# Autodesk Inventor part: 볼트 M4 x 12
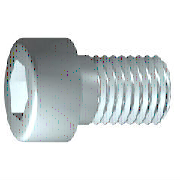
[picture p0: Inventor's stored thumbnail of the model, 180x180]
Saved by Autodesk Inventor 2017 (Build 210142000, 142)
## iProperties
IsCustomPart: 0
Created: 2012-02
Part Number: 볼트 M4 x 12
Material: 스테인리스강
Description: 6각 소켓 머리 캡 나사
Document SubType Name: Modeling
Standard: ISO 4762
Designer: mduedu
Standard Revision: Fourth edition 2004-03-01
Standards Organization: ISO
Language: ko-KR
Size Designation: M4 x 8
Categories: <MemberInstance><Categories><Category DisplayName="조임쇠" InternalName="e4da775c-781d-43d5-af7c-5136215cf5a6" Mnemonic="FSTN"><Category DisplayName="볼트" InternalN
Density: 8.08 g/cm^3
Mass: 2.2972 g
Surface Area: 3.30853 cm^2
Volume: 0.284306 cm^3
Appearance: 반광택
Author: mduedu
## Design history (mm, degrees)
sketch "스케치1"
  geometry: L1 (-1, 0)-(12, 0); L2 (12, 0)-(12, 2); L3 (12, 2)-(1.75, 2); L4 (1.75, 2)-(1.32, 2); L5 (1.32, 2)-(0, 2); L6 (0, 2)-(0, 3.5); L7 (0, 3.5)-(-4, 3.5); L8 (-4, 3.5)-(-4, 1.732); L9 (-4, 1.732)-(-2, 1.732); L10 (-2, 1.732)-(-1, 0); L11 (-7.2, 0)-(15.2, 0) reference; L12 (0, -0.7)-(0, 4.2) reference; L13 (1.75, 2)-(0, 2)
  constraints: 22 end point, 6 parallel, 2 collinear, 2 perpendicular, 1 horizontal, 1 point on line
  dimensions: "d1" = 10.25 distance from line of L3.end L2 (= GEL); "d2" = 0.42952 distance of L4.end L3.end (computed from GAL); "d3" = 4 distance between parallel lines of L8 L6 (= KOH); "d4" = 2 distance of L8.end L9.end (= INTI); "d5" = 60 deg angle of L10 L1; "d6" = 4 diameter of L3 L1 (= GD); "d7" = 4 diameter of L5 L1 (= BDM); "d8" = 3.4641 diameter of L9 L1 (= 1.1547 x SW); "d9" = 7 diameter of L7 L1 (= KOD); "d26" = 12 distance between parallel lines of L12 L2 (= NLG)
revolve "본체" sketch "스케치1" stored, may be unused: angle "d10" = 90 deg
sketch "스케치2"
  geometry: L1 (0, -4.9)-(0, 4.9) reference; L2 (-4.9, 0)-(4.9, 0) reference; L3 (1.732, 0)-(0.866, -1.5); L4 (0.866, -1.5)-(-0.866, -1.5); L5 (-0.866, -1.5)-(-1.732, 0); L6 (-1.732, 0)-(-0.866, 1.5); L7 (-0.866, 1.5)-(0.866, 1.5); L8 (0.866, 1.5)-(1.732, 0); 2 further points
  constraints: 12 end point, 1 coincident, 1 horizontal alignment, 1 point on line, 12 other
extrude "슬롯" join sketch "스케치2" stored distance "d11" = 10; taper "d12" = 0 deg
workplane "Work Plane1"
fillet "Fillet2" dims "d30" = 0.1 (= R)
body "Solid1"
fillet "모깎기1" dims "d17" = 0.4 (= RR)
feature "스레드" dims "d13" = 10.25 (= GEL), "d14" = 0
chamfer "모따기1" distance "d15" = 0.42941 (= -0.5 x SPD + 0.5 x GD); stored, may be unused: second distance "d16" = 0.42941 (= GUL), angle "d27" = 45 deg
other parameters: "GD" = 4 [user parameter; used in 2 equation terms], "NLG" = 12 [user parameter; used in 1 equation term], "GEL" = 10.25 [user parameter; used in 2 equation terms], "KOD" = 7 [user parameter; used in 1 equation term], "KOH" = 4 [user parameter; used in 1 equation term], "INTI" = 2 [user parameter; used in 1 equation term], "GAL" = 0.42941 (= 0.61345 x PTC) [user parameter; used in 1 equation term], "GUL" = 0.42941 (= 0.61345 x PTC) [user parameter; used in 1 equation term], "BDM" = 4 (= NND) [user parameter; used in 1 equation term], "SW" = 3 [user parameter; used in 2 equation terms], "RR" = 0.4 [user parameter; used in 1 equation term], "SPD" = 3.14117 (= NND - 1.2269 x PTC) [user parameter; used in 1 equation term], "d19" = 0, "d28" = 0, "d29" = 0, "R" = 0.1 [user parameter; used in 1 equation term], "TOA" = 30 deg [user parameter], "GD1" = 3.14117 (= THREADDIA - 1.2269 x PTC) [user parameter], "THREADDIA" = 4 [user parameter; used in 1 equation term], "FAWI" = 45 deg [user parameter], "TPU" = 14.28571 (computed from PTC) [user parameter], "PTC" = 0.7 [user parameter; used in 5 equation terms], "NND" = 4 [user parameter; used in 2 equation terms], "E0" = 3.465 (= 1.155 x SW) [user parameter]
